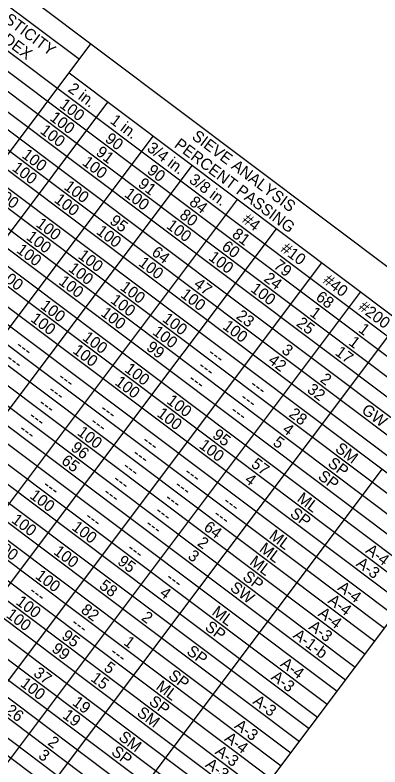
# Model space of a CAD drawing. Extents: x 627484.2 to 627517.5, y 367968.7 to 367996.9.
# Drawn here: x 627495.744 to 627497.501, y 367986.94 to 367990.557 of the extents above; entities that cross this region are included whole.
import ezdxf

# ---------------------------------------------------------------- set-up
doc = ezdxf.new("R2010")
doc.units = 0
doc.layers.add('Default', color=7, linetype='Continuous')

msp = doc.modelspace()

# ---------------------------------------------------------------- linework, layer by layer
at = {"layer": 'Default'}
for p, q in [((627493.1196, 367992.664), (627498.3625, 367988.727)), ((627492.9586, 367992.4496), (627498.2015, 367988.5126)), ((627492.9118, 367992.3872), (627498.1547, 367988.4503)), ((627492.8649, 367992.3248), (627498.1078, 367988.3879)), ((627492.8181, 367992.2625), (627498.061, 367988.3255)), ((627492.7771, 367992.2079), (627498.02, 367988.2709)), ((627492.7303, 367992.1455), (627497.9732, 367988.2086)), ((627492.6834, 367992.0832), (627497.9263, 367988.1462)), ((627492.6425, 367992.0286), (627497.8854, 367988.0916)), ((627492.5956, 367991.9662), (627497.8385, 367988.0293)), ((627492.5488, 367991.9038), (627497.7917, 367987.9669)), ((627492.5019, 367991.8415), (627497.7449, 367987.9045)), ((627492.461, 367991.7869), (627497.7039, 367987.8499)), ((627492.4141, 367991.7245), (627497.657, 367987.7876)), ((627492.3673, 367991.6621), (627497.6102, 367987.7252)), ((627492.3263, 367991.6076), (627497.5692, 367987.6706)), ((627492.2795, 367991.5452), (627497.5224, 367987.6082)), ((627492.2326, 367991.4828), (627497.4755, 367987.5459)), ((627492.1858, 367991.4204), (627497.4287, 367987.4835)), ((627492.139, 367991.3581), (627497.3819, 367987.4211)), ((627492.0921, 367991.2957), (627497.335, 367987.3587)), ((627492.0511, 367991.2411), (627497.2941, 367987.3042)), ((627494.8998, 367991.2114), (627496.0537, 367990.3449)), ((627492.0043, 367991.1787), (627497.2472, 367987.2418)), ((627491.9575, 367991.1164), (627497.2004, 367987.1794)), ((627491.9165, 367991.0618), (627497.1594, 367987.1248)), ((627491.8697, 367990.9994), (627497.1126, 367987.0625)), ((627491.8287, 367990.9448), (627497.0716, 367987.0079)), ((627491.7818, 367990.8825), (627497.0247, 367986.9455)), ((627491.735, 367990.8201), (627496.9779, 367986.8832)), ((627491.6882, 367990.7577), (627496.9311, 367986.8208)), ((627491.6413, 367990.6954), (627496.8842, 367986.7584)), ((627491.6003, 367990.6408), (627496.8433, 367986.7038)), ((627491.5535, 367990.5784), (627496.7964, 367986.6415)), ((627491.5067, 367990.516), (627496.7496, 367986.5791)), ((627491.4657, 367990.4615), (627496.7086, 367986.5245)), ((627494.1802, 367987.85), (627496.1093, 367990.419)), ((627491.4189, 367990.3991), (627496.6618, 367986.4621)), ((627491.372, 367990.3367), (627496.6149, 367986.3998)), ((627491.331, 367990.2821), (627496.5739, 367986.3452)), ((627496.0039, 367990.2787), (627497.5944, 367989.0843)), ((627494.3673, 367987.7095), (627496.191, 367990.1382)), ((627494.5856, 367987.5456), (627496.4093, 367989.9742)), ((627494.7728, 367987.4051), (627496.5965, 367989.8337)), ((627494.9911, 367987.2412), (627496.8148, 367989.6698)), ((627495.1782, 367987.1006), (627497.0019, 367989.5293)), ((627495.3965, 367986.9367), (627497.2202, 367989.3654)), ((627495.5836, 367986.7962), (627497.4073, 367989.2249)), ((627495.7707, 367986.6557), (627497.6998, 367989.2247)), ((627496.4334, 367986.1581), (627498.3625, 367988.727)), ((627496.0592, 367986.4391), (627497.5111, 367988.3726))]:
    msp.add_line(p, q, dxfattribs=at)

# ---------------------------------------------------------------- texts
for s, p in [('PLASTICITY', (627495.5769, 367990.6104)), ('INDEX', (627495.6212, 367990.474)), ('2 in.', (627495.9949, 367990.1931)), ('100', (627495.9543, 367990.1169)), ('100', (627495.9075, 367990.0545)), ('1 in.', (627496.1976, 367990.0409)), ('100', (627495.8607, 367989.9922)), ('90', (627496.1733, 367989.9525)), ('SIEVE ANALYSIS', (627496.5912, 367989.9646)), ('3/4 in.', (627496.375, 367989.9077)), ('PERCENT PASSING', (627496.5064, 367989.9251)), ('100', (627495.7728, 367989.8752)), ('91', (627496.1293, 367989.888)), ('100', (627496.0634, 367989.8399)), ('100', (627495.726, 367989.8128)), ('90', (627496.376, 367989.8003)), ('3/8 in.', (627496.5777, 367989.7555)), ('100', (627495.9756, 367989.723)), ('91', (627496.332, 367989.7358)), ('100', (627495.6382, 367989.6959)), ('100', (627496.2661, 367989.6877)), ('100', (627495.9287, 367989.6606)), ('84', (627496.5787, 367989.6481)), ('80', (627496.5319, 367989.5857)), ('100', (627495.8409, 367989.5437)), ('95', (627496.1955, 367989.5578)), ('#4', (627496.8328, 367989.564)), ('100', (627496.1314, 367989.5084)), ('100', (627496.4688, 367989.5355)), ('100', (627495.7941, 367989.4813)), ('81', (627496.7843, 367989.4937)), ('60', (627496.7346, 367989.4335)), ('100', (627495.7472, 367989.4189)), ('64', (627496.3972, 367989.4064)), ('#10', (627497.0191, 367989.4241)), ('100', (627496.0436, 367989.3914)), ('100', (627496.6715, 367989.3833)), ('100', (627495.9968, 367989.3291)), ('100', (627496.3341, 367989.3562)), ('79', (627496.9844, 367989.3434)), ('100', (627495.6594, 367989.302)), ('24', (627496.9373, 367989.2813)), ('100', (627495.9499, 367989.2667)), ('47', (627496.6002, 367989.2539)), ('#40', (627497.2218, 367989.2718)), ('100', (627496.2463, 367989.2392)), ('100', (627496.8742, 367989.2311)), ('100', (627496.1995, 367989.1769)), ('100', (627496.5369, 367989.204)), ('68', (627497.1876, 367989.1909)), ('100', (627495.8621, 367989.1498)), ('#200', (627497.3926, 367989.1436)), ('100', (627496.1527, 367989.1145)), ('23', (627496.8042, 367989.1008)), ('1', (627497.1591, 367989.1147)), ('100', (627495.8153, 367989.0874)), ('100', (627496.449, 367989.087)), ('25', (627497.0942, 367989.0659)), ('100', (627496.7396, 367989.0517)), ('1', (627497.393, 367989.0366)), ('100', (627496.0648, 367988.9975)), ('100', (627496.4022, 367989.0246)), ('1', (627497.3462, 367988.9742)), ('---', (627495.7439, 367988.9581)), ('100', (627496.018, 367988.9352)), ('99', (627496.3718, 367988.9499)), ('3', (627497.0232, 367988.9363)), ('17', (627497.2806, 367988.9259)), ('---', (627496.6682, 367988.9225)), ('---', (627495.697, 367988.8957)), ('42', (627496.9587, 367988.8872)), ('100', (627496.2675, 367988.8453)), ('---', (627496.6213, 367988.8601)), ('---', (627495.9466, 367988.8059)), ('100', (627496.2207, 367988.7829)), ('---', (627496.5745, 367988.7977)), ('2', (627497.2089, 367988.7968)), ('---', (627496.8709, 367988.7703)), ('32', (627497.1458, 367988.7467)), ('---', (627495.8998, 367988.7435)), ('100', (627496.4703, 367988.6931)), ('---', (627496.824, 367988.7079)), ('---', (627495.8529, 367988.6811)), ('---', (627496.1493, 367988.6537)), ('GW', (627497.4078, 367988.6475)), ('---', (627495.8061, 367988.6188)), ('100', (627496.4234, 367988.6307)), ('---', (627496.7772, 367988.6455)), ('28', (627497.0585, 367988.6293)), ('---', (627496.1025, 367988.5913)), ('---', (627495.7592, 367988.5564)), ('100', (627496.0392, 367988.5412)), ('95', (627496.6902, 367988.5279)), ('4', (627497.0272, 367988.5553)), ('5', (627496.9814, 367988.4922)), ('96', (627496.0087, 367988.4666)), ('---', (627496.352, 367988.5015)), ('100', (627496.6261, 367988.4785)), ('SM', (627497.2807, 367988.4625)), ('---', (627496.3052, 367988.4391)), ('65', (627495.9628, 367988.4036)), ('57', (627496.8766, 367988.3879)), ('SP', (627497.2452, 367988.3917)), ('---', (627496.2583, 367988.3767)), ('---', (627496.5547, 367988.3492)), ('4', (627496.8457, 367988.3136)), ('SP', (627497.1983, 367988.3293)), ('---', (627495.8741, 367988.2872)), ('---', (627496.2115, 367988.3143)), ('100', (627495.8109, 367988.2372)), ('---', (627496.1647, 367988.252)), ('---', (627496.5079, 367988.2869)), ('---', (627496.461, 367988.2245)), ('ML', (627497.0974, 367988.2221)), ('---', (627496.7418, 367988.2087)), ('---', (627496.4142, 367988.1621)), ('---', (627496.695, 367988.1464)), ('SP', (627497.0637, 367988.15)), ('100', (627495.7231, 367988.1202)), ('---', (627496.0768, 367988.135)), ('100', (627496.0136, 367988.085)), ('---', (627496.3674, 367988.0997)), ('64', (627496.648, 367988.0841)), ('ML', (627496.9628, 367988.0428)), ('100', (627495.6353, 367988.0033)), ('2', (627496.6176, 367988.0094)), ('ML', (627496.916, 367987.9804)), ('100', (627495.9258, 367987.968)), ('---', (627496.2796, 367987.9828)), ('3', (627496.5721, 367987.946)), ('A-4', (627497.4274, 367987.9743)), ('95', (627496.2335, 367987.9198)), ('ML', (627496.8691, 367987.9181)), ('A-3', (627497.3822, 367987.9108)), ('100', (627495.838, 367987.8511)), ('SP', (627496.8353, 367987.8459)), ('58', (627496.1454, 367987.8031)), ('---', (627496.4667, 367987.8423)), ('SW', (627496.775, 367987.7937)), ('A-4', (627497.2928, 367987.795)), ('---', (627495.8075, 367987.7764)), ('4', (627496.4359, 367987.7679)), ('A-4', (627497.2459, 367987.7327)), ('100', (627495.7443, 367987.7263)), ('100', (627495.6975, 367987.6639)), ('82', (627496.0571, 367987.6865)), ('ML', (627496.6876, 367987.6764)), ('A-4', (627497.1991, 367987.6703)), ('2', (627496.3483, 367987.6507)), ('---', (627496.0103, 367987.6242)), ('SP', (627496.6538, 367987.6042)), ('A-3', (627497.1538, 367987.6067)), ('95', (627495.9642, 367987.5612)), ('A-1-b', (627497.0784, 367987.5658)), ('1', (627496.2631, 367987.5318)), ('99', (627495.9166, 367987.4994)), ('SP', (627496.566, 367987.4873)), ('---', (627496.1974, 367987.4836)), ('5', (627496.1676, 367987.4085)), ('A-4', (627497.0176, 367987.4286)), ('37', (627495.8289, 367987.3824)), ('SP', (627496.4782, 367987.3703)), ('100', (627495.7655, 367987.3324)), ('15', (627496.1045, 367987.3583)), ('A-3', (627496.9724, 367987.365)), ('ML', (627496.4183, 367987.3177)), ('19', (627496.0159, 367987.2419)), ('SP', (627496.3845, 367987.2456)), ('A-3', (627496.8845, 367987.2481)), ('26', (627495.694, 367987.2032)), ('SM', (627496.3264, 367987.1917)), ('19', (627495.9691, 367987.1795)), ('A-3', (627496.7967, 367987.1311)), ('2', (627495.8975, 367987.0504)), ('SM', (627496.2386, 367987.0747)), ('A-4', (627496.7483, 367987.0699)), ('SP', (627496.203, 367987.0039)), ('3', (627495.852, 367986.987)), ('A-3', (627496.7031, 367987.0064)), ('A-3', (627496.6562, 367986.944))]:
    msp.add_text(s, height=0.055, rotation=323.0968, dxfattribs=at).set_placement(p)

doc.saveas('drawing.dxf')
